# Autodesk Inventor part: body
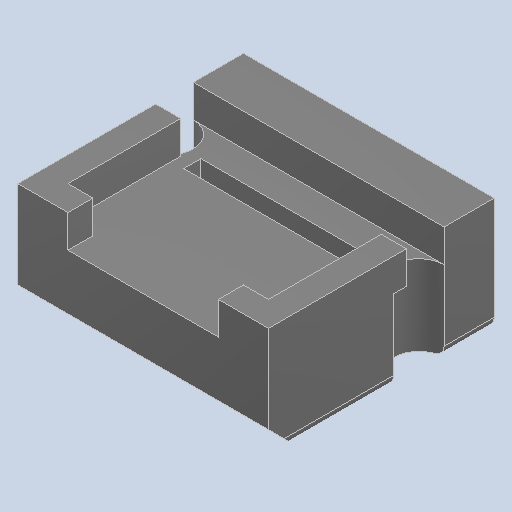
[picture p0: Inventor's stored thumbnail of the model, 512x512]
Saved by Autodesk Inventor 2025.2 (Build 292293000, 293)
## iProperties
Created: 2025-04
Part Number: body
Material: Generic
Description: PART--DESC
Document SubType Name: Modeling
Designer: BennF
Density: 1 g/cm^3
Appearance: Default
Author: BennF
Revision Number: NONE
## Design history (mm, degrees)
feature "Solid"
body "Solid1"
